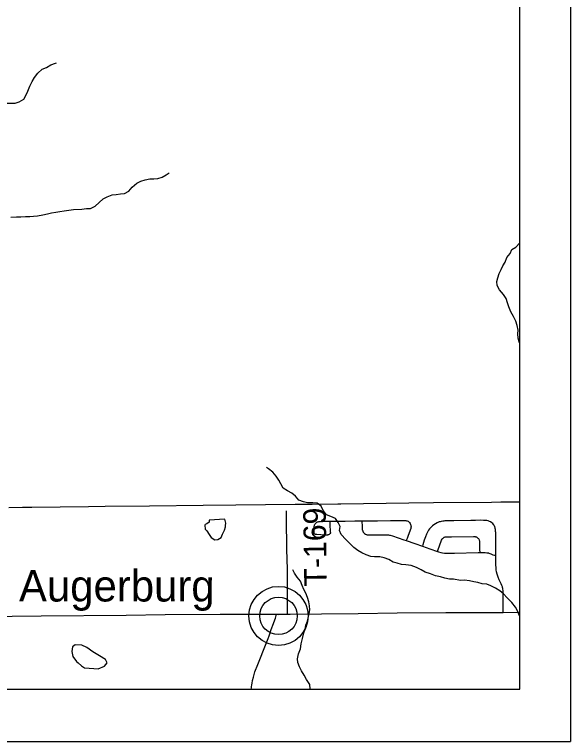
# Model space of a CAD drawing. Extents: x 0 to 34, y 0 to 22.
# Drawn here: x 28.598 to 29.999, y 9.775 to 11.606 of the extents above; entities that cross this region are included whole.
import ezdxf

# ---------------------------------------------------------------- set-up
doc = ezdxf.new("R2010")
doc.units = 0
for name, color, linetype in [('GM_X_Corporation', 7, 'Continuous'), ('GM_X_County_Road', 7, 'Continuous'), ('GM_X_Minor_Lake', 7, 'Continuous'), ('GM_X_Minor_River', 7, 'Continuous'), ('GM_X_Township_Road', 7, 'Continuous'), ('GM_X_Township_Road_Text', 7, 'Continuous'), ('GM_X_Unincorporated', 7, 'Continuous'), ('GM_X_Unincorporated_Location', 7, 'Continuous'), ('GM_X_Unincorporated_Text', 7, 'Continuous'), ('SH_Data', 7, 'Continuous')]:
    doc.layers.add(name, color=color, linetype=linetype)

msp = doc.modelspace()

# ---------------------------------------------------------------- linework, layer by layer
at = {"layer": 'GM_X_Corporation'}
msp.add_lwpolyline([(27.921, 11.6881), (27.921, 11.605), (27.9209, 11.5591), (27.9213, 11.5157), (27.922, 11.4402), (27.9221, 11.428), (27.9223, 11.4042), (27.9223, 11.3879), (27.922, 11.3573), (27.922, 11.3409), (27.9227, 11.2961), (27.9232, 11.1955), (27.9232, 11.1514), (27.9237, 11.0691), (27.9238, 11.0659), (27.9241, 11.0633), (27.9246, 11.0606), (27.9211, 10.9894), (27.9256, 10.5454), (27.929, 10.0627), (27.93, 9.9067), (29.8715, 9.9067), (29.8715, 12.7899)], dxfattribs=at)
at = {"layer": 'GM_X_County_Road'}
msp.add_line((29.8292, 10.1001), (29.8715, 10.1003), dxfattribs=at)
for points in [[(28.2039, 10.0857), (28.2681, 10.0863), (28.3465, 10.0873), (28.4927, 10.0891), (28.5921, 10.0902), (28.6653, 10.0911), (28.8794, 10.0932), (28.9779, 10.0944), (29.1166, 10.0952), (29.1272, 10.0951), (29.1576, 10.0952), (29.2577, 10.0954)], [(29.2577, 10.0954), (29.2737, 10.0956), (29.2863, 10.0955)], [(29.2863, 10.0955), (29.2929, 10.0955), (29.3717, 10.0961), (29.4637, 10.0972), (29.5625, 10.0985), (29.6851, 10.0994), (29.8292, 10.1001)]]:
    msp.add_lwpolyline(points, dxfattribs=at)
at = {"layer": 'GM_X_Minor_Lake'}
for p, q in [((29.1284, 10.3344), (29.0886, 10.332)), ((28.7746, 9.96), (28.7981, 9.9588))]:
    msp.add_line(p, q, dxfattribs=at)
for points in [[(29.0886, 10.332), (29.0883, 10.3271), (29.083, 10.3229), (29.0781, 10.3217), (29.0778, 10.3194), (29.0783, 10.3099), (29.0829, 10.3054), (29.0883, 10.2963), (29.0933, 10.2884), (29.1028, 10.2828), (29.1104, 10.2837), (29.1186, 10.2887), (29.1223, 10.2967), (29.1268, 10.3067), (29.1297, 10.3151), (29.13, 10.3192), (29.1304, 10.3246), (29.1288, 10.3314), (29.1284, 10.3344)], [(28.7981, 9.9588), (28.8091, 9.9578), (28.8246, 9.9644), (28.8313, 9.9729), (28.8274, 9.9812), (28.8122, 9.9905), (28.7954, 10.0009), (28.7805, 10.0117), (28.7675, 10.0177), (28.7505, 10.0179), (28.7437, 10.0132), (28.7427, 10.0011), (28.7451, 9.9886), (28.754, 9.9761), (28.7586, 9.9728), (28.767, 9.9653), (28.7746, 9.96)]]:
    msp.add_lwpolyline(points, dxfattribs=at)
at = {"layer": 'GM_X_Minor_River'}
for points in [[(28.5796, 11.3823), (28.5996, 11.3826), (28.6098, 11.3861), (28.6215, 11.3927), (28.6267, 11.4023), (28.6318, 11.4129), (28.6366, 11.4251), (28.6422, 11.437), (28.6481, 11.4473), (28.6563, 11.4584), (28.6672, 11.468), (28.6781, 11.4723), (28.6894, 11.4793), (28.7015, 11.4832), (28.7034, 11.4844)], [(28.5885, 11.0958), (28.6028, 11.096), (28.6138, 11.0965), (28.6259, 11.097), (28.6362, 11.0971), (28.646, 11.0984), (28.6562, 11.0992), (28.6691, 11.1017), (28.6812, 11.1041), (28.6914, 11.1065), (28.7023, 11.1081), (28.7121, 11.1098), (28.7231, 11.1114), (28.7348, 11.1131), (28.7466, 11.1151), (28.7678, 11.1154), (28.7791, 11.117), (28.7893, 11.1175), (28.8014, 11.1234), (28.8115, 11.1322), (28.8216, 11.1414), (28.8318, 11.1465), (28.8439, 11.1519), (28.8537, 11.1524), (28.8647, 11.1545), (28.8753, 11.155), (28.8858, 11.1608), (28.8948, 11.1711), (28.906, 11.1815), (28.9166, 11.1862), (28.9275, 11.1898), (28.9392, 11.1918), (28.9494, 11.1923), (28.9593, 11.1928), (28.9699, 11.1959), (28.98, 11.2018), (28.9879, 11.2075)], [(29.8715, 10.7769), (29.8702, 10.7812), (29.8675, 10.7911), (29.8662, 10.8013), (29.8672, 10.8112), (29.8652, 10.8222), (29.8617, 10.8332), (29.8555, 10.8449), (29.8489, 10.8566), (29.8442, 10.8694), (29.8403, 10.8796), (29.8368, 10.8906), (29.8303, 10.9008), (29.8203, 10.9128), (29.8145, 10.9237), (29.814, 10.9332), (29.8158, 10.9427), (29.8191, 10.9538), (29.8243, 10.9633), (29.8287, 10.9729), (29.835, 10.9824), (29.8391, 10.9935), (29.8469, 11.0042), (29.8513, 11.0142), (29.8615, 11.0203), (29.8712, 11.0307), (29.8715, 11.0311)], [(29.8715, 10.0905), (29.8707, 10.0917), (29.8664, 10.1023), (29.8606, 10.1129), (29.8514, 10.1249), (29.8396, 10.1365), (29.8307, 10.1471), (29.8212, 10.1542), (29.8105, 10.1613), (29.7987, 10.1672), (29.7884, 10.1712), (29.7767, 10.1715), (29.766, 10.1752), (29.7554, 10.1773), (29.7444, 10.1798), (29.7323, 10.1808), (29.7224, 10.1807), (29.7042, 10.1836), (29.6944, 10.1834), (29.6826, 10.1863), (29.6716, 10.1893), (29.6587, 10.1921), (29.6461, 10.1969), (29.6328, 10.2013), (29.6225, 10.2069), (29.6111, 10.2128), (29.5978, 10.2184), (29.5841, 10.2201), (29.5731, 10.2208), (29.5625, 10.2241), (29.5519, 10.2262), (29.5415, 10.2329), (29.5298, 10.237), (29.5188, 10.2395), (29.5055, 10.2401), (29.4956, 10.2407), (29.4846, 10.2452), (29.4732, 10.2496), (29.4629, 10.2559), (29.453, 10.2634), (29.443, 10.2732), (29.4334, 10.2837), (29.4212, 10.2961), (29.4169, 10.3059), (29.4183, 10.3162), (29.414, 10.326), (29.4071, 10.3365), (29.3949, 10.3413), (29.3839, 10.3457), (29.3762, 10.3563), (29.3711, 10.3672), (29.3604, 10.3747), (29.3498, 10.3761), (29.3366, 10.3763), (29.3259, 10.3781), (29.3149, 10.3825), (29.3065, 10.3927), (29.2969, 10.4005), (29.2859, 10.4065), (29.2752, 10.4128), (29.2694, 10.4234), (29.264, 10.4332), (29.2574, 10.4434), (29.2486, 10.4535), (29.2383, 10.4614), (29.2329, 10.4647)], [(29.3434, 9.9067), (29.3433, 9.9071), (29.3424, 9.9185), (29.334, 9.9313), (29.3278, 9.9415), (29.3212, 9.9524), (29.3158, 9.9626), (29.3123, 9.9736), (29.311, 9.9834), (29.3139, 9.9952), (29.3187, 10.0082), (29.3201, 10.0207), (29.3241, 10.0344), (29.3274, 10.0482), (29.3303, 10.0577), (29.3324, 10.0676), (29.3365, 10.0775), (29.3408, 10.0969), (29.3419, 10.1064), (29.3417, 10.1163), (29.3397, 10.1269), (29.3362, 10.1371), (29.3319, 10.1481), (29.3273, 10.1579), (29.3226, 10.1681), (29.3187, 10.1787), (29.3103, 10.1888), (29.3037, 10.199), (29.2994, 10.2073)]]:
    msp.add_lwpolyline(points, dxfattribs=at)
at = {"layer": 'GM_X_Township_Road'}
for points in [[(29.8715, 10.3777), (29.8631, 10.3776), (29.8233, 10.3772), (29.8003, 10.377), (29.6543, 10.3759), (29.5916, 10.3752), (29.4207, 10.3728), (29.4126, 10.3728), (29.3483, 10.3718), (29.3049, 10.3718), (29.1561, 10.3697), (29.0736, 10.3691), (28.9382, 10.3677), (28.8262, 10.3668), (28.784, 10.366), (28.6412, 10.3642), (28.6176, 10.3641), (28.5834, 10.3633)], [(29.2863, 10.0955), (29.2863, 10.1008), (29.2857, 10.2078), (29.2844, 10.2593), (29.2839, 10.2854), (29.2837, 10.3093), (29.2838, 10.33), (29.2838, 10.3393), (29.2838, 10.3467), (29.2837, 10.3535), (29.2836, 10.356)], [(29.3943, 10.3011), (29.3941, 10.2997), (29.3939, 10.2992), (29.3932, 10.2982), (29.3925, 10.2975), (29.3918, 10.297), (29.3907, 10.2964), (29.3893, 10.2957), (29.3879, 10.2952), (29.3866, 10.2949), (29.385, 10.2945), (29.3835, 10.2943), (29.3819, 10.2942), (29.3804, 10.2942), (29.3699, 10.2951), (29.36, 10.2958), (29.3575, 10.2962), (29.3564, 10.2965), (29.3558, 10.2968), (29.3547, 10.2974), (29.3542, 10.2979), (29.3535, 10.2989), (29.3532, 10.2999), (29.3531, 10.3006), (29.353, 10.3056), (29.353, 10.3118), (29.3531, 10.3148), (29.3534, 10.3174), (29.3538, 10.3191), (29.3543, 10.3204), (29.355, 10.3216), (29.3558, 10.323), (29.3571, 10.3245), (29.3585, 10.3259), (29.3601, 10.327), (29.3617, 10.3279), (29.3635, 10.3284), (29.3649, 10.3287), (29.3672, 10.329), (29.3695, 10.3293), (29.3734, 10.3294), (29.3938, 10.3295), (29.397, 10.3296), (29.4206, 10.3299), (29.4312, 10.3301), (29.4554, 10.3305), (29.4737, 10.3307), (29.5132, 10.331), (29.5455, 10.3316), (29.5728, 10.3318), (29.5803, 10.3318), (29.5821, 10.3317), (29.5833, 10.3316), (29.5846, 10.3314), (29.586, 10.331), (29.5875, 10.3305), (29.5898, 10.3294), (29.5908, 10.3287), (29.5918, 10.3279), (29.5935, 10.3261), (29.5952, 10.3235), (29.5963, 10.3213), (29.5967, 10.32), (29.597, 10.3189), (29.5972, 10.3177), (29.5973, 10.3158), (29.5973, 10.3146), (29.5972, 10.3134), (29.5966, 10.3109), (29.5904, 10.2934), (29.5877, 10.2865), (29.5855, 10.2807)], [(29.3943, 10.3011), (29.3938, 10.3234), (29.3938, 10.3247), (29.3938, 10.3295)], [(29.4737, 10.3307), (29.4737, 10.3274), (29.4738, 10.3192), (29.4738, 10.3154), (29.474, 10.312), (29.4741, 10.3103), (29.4745, 10.3082), (29.4748, 10.3067), (29.4757, 10.3047), (29.4771, 10.3022), (29.4785, 10.3003), (29.4803, 10.2987), (29.4822, 10.2974), (29.4843, 10.2964), (29.4855, 10.2959), (29.4871, 10.2956), (29.488, 10.2954), (29.4901, 10.2952), (29.4962, 10.2952), (29.5043, 10.2952), (29.5235, 10.2955), (29.5373, 10.2954), (29.5389, 10.2953), (29.5408, 10.2952), (29.5428, 10.2948), (29.5448, 10.2943), (29.5508, 10.2925), (29.5796, 10.2827), (29.5855, 10.2807), (29.6067, 10.2734), (29.6263, 10.2664), (29.6447, 10.2598), (29.664, 10.2531), (29.667, 10.2521), (29.6723, 10.2506), (29.6765, 10.2499), (29.682, 10.2494), (29.6912, 10.2492), (29.7067, 10.2494), (29.7663, 10.2506), (29.7704, 10.2508), (29.7782, 10.251), (29.7844, 10.2509), (29.7888, 10.2504), (29.7926, 10.2496), (29.7938, 10.2493), (29.7956, 10.2486), (29.7985, 10.2473), (29.8033, 10.2452), (29.8075, 10.2437), (29.811, 10.2427)], [(29.8292, 10.1001), (29.8292, 10.1051), (29.8294, 10.1503), (29.8292, 10.1549), (29.829, 10.1581), (29.8287, 10.1602), (29.8282, 10.1623), (29.8275, 10.1646), (29.8264, 10.1673), (29.8246, 10.1715), (29.8195, 10.1822), (29.8167, 10.189), (29.8145, 10.196), (29.8129, 10.2025), (29.8122, 10.2073), (29.8117, 10.2116), (29.8114, 10.2208), (29.811, 10.2427), (29.8109, 10.2605), (29.8107, 10.2909), (29.8107, 10.2934), (29.8107, 10.3014), (29.8106, 10.3039), (29.8105, 10.3065), (29.8102, 10.3089), (29.8098, 10.3109), (29.8094, 10.3129), (29.8089, 10.3146), (29.8083, 10.3159), (29.8076, 10.3175), (29.807, 10.3184), (29.8059, 10.3201), (29.8049, 10.3215), (29.8032, 10.3235), (29.8008, 10.3256), (29.7977, 10.3278), (29.7948, 10.3293), (29.7931, 10.33), (29.7918, 10.3304), (29.7887, 10.3312), (29.7855, 10.3316), (29.7803, 10.3318), (29.773, 10.3319), (29.76, 10.3317), (29.7482, 10.3316), (29.7053, 10.3308), (29.6942, 10.3305), (29.6829, 10.3303), (29.68, 10.3301), (29.6773, 10.3299), (29.6731, 10.3291), (29.6705, 10.3284), (29.6681, 10.3277), (29.6634, 10.3257), (29.6589, 10.3234), (29.6547, 10.3206), (29.6512, 10.3179), (29.6471, 10.314), (29.6442, 10.3106), (29.6416, 10.307), (29.6388, 10.3021), (29.6363, 10.297), (29.6336, 10.29), (29.6308, 10.2817), (29.6275, 10.2704), (29.6263, 10.2664)], [(29.664, 10.2531), (29.6649, 10.2556), (29.6745, 10.2822), (29.6756, 10.2845), (29.6761, 10.2853), (29.6766, 10.286), (29.678, 10.2873), (29.6789, 10.2881), (29.6799, 10.2887), (29.681, 10.2892), (29.682, 10.2896), (29.6835, 10.29), (29.6851, 10.2901), (29.6996, 10.2904), (29.7549, 10.2909), (29.7586, 10.2908), (29.7595, 10.2907), (29.7605, 10.2905), (29.7613, 10.2902), (29.7622, 10.2899), (29.7638, 10.289), (29.7653, 10.2879), (29.7661, 10.2871), (29.767, 10.286), (29.7684, 10.284), (29.7689, 10.2829), (29.7694, 10.2817), (29.7698, 10.2805), (29.77, 10.2787), (29.7702, 10.2768), (29.7702, 10.2708), (29.7703, 10.2583), (29.7704, 10.2508)], [(29.1947, 9.9067), (29.1951, 9.9098), (29.1955, 9.9128), (29.1962, 9.9177), (29.1968, 9.9213), (29.1981, 9.9286), (29.1999, 9.9371), (29.2017, 9.9436), (29.2038, 9.9501), (29.2108, 9.9683), (29.232, 10.0217), (29.2369, 10.0345), (29.2394, 10.0408), (29.2452, 10.0566), (29.2508, 10.0718), (29.254, 10.0812), (29.2554, 10.0854), (29.2564, 10.0886), (29.2571, 10.0923), (29.2577, 10.0954)], [(29.2577, 10.0954), (29.2737, 10.0956), (29.2863, 10.0955)]]:
    msp.add_lwpolyline(points, dxfattribs=at)
at = {"layer": 'GM_X_Unincorporated'}
for radius in [0.0744, 0.0472]:
    msp.add_circle((29.2633, 10.0911), radius, dxfattribs=at)
at = {"layer": 'GM_X_Unincorporated_Location'}
msp.add_line((29.2633, 10.0911), (29.2633, 10.0911), dxfattribs=at)
at = {"layer": 'SH_Data'}
for p in [(29.9992, 16.7749), (22.9992, 9.7749)]:
    msp.add_line(p, (29.9992, 9.7749), dxfattribs=at)

# ---------------------------------------------------------------- texts
at = {"layer": 'GM_X_Township_Road_Text'}
msp.add_text('T-169', height=0.05682, rotation=90.8319, dxfattribs=at).set_placement((29.3851, 10.1657))
at = {"layer": 'GM_X_Unincorporated_Text'}
msp.add_text('Augerburg', height=0.07898, rotation=0, dxfattribs=at).set_placement((28.6091, 10.1274))

doc.saveas('drawing.dxf')
